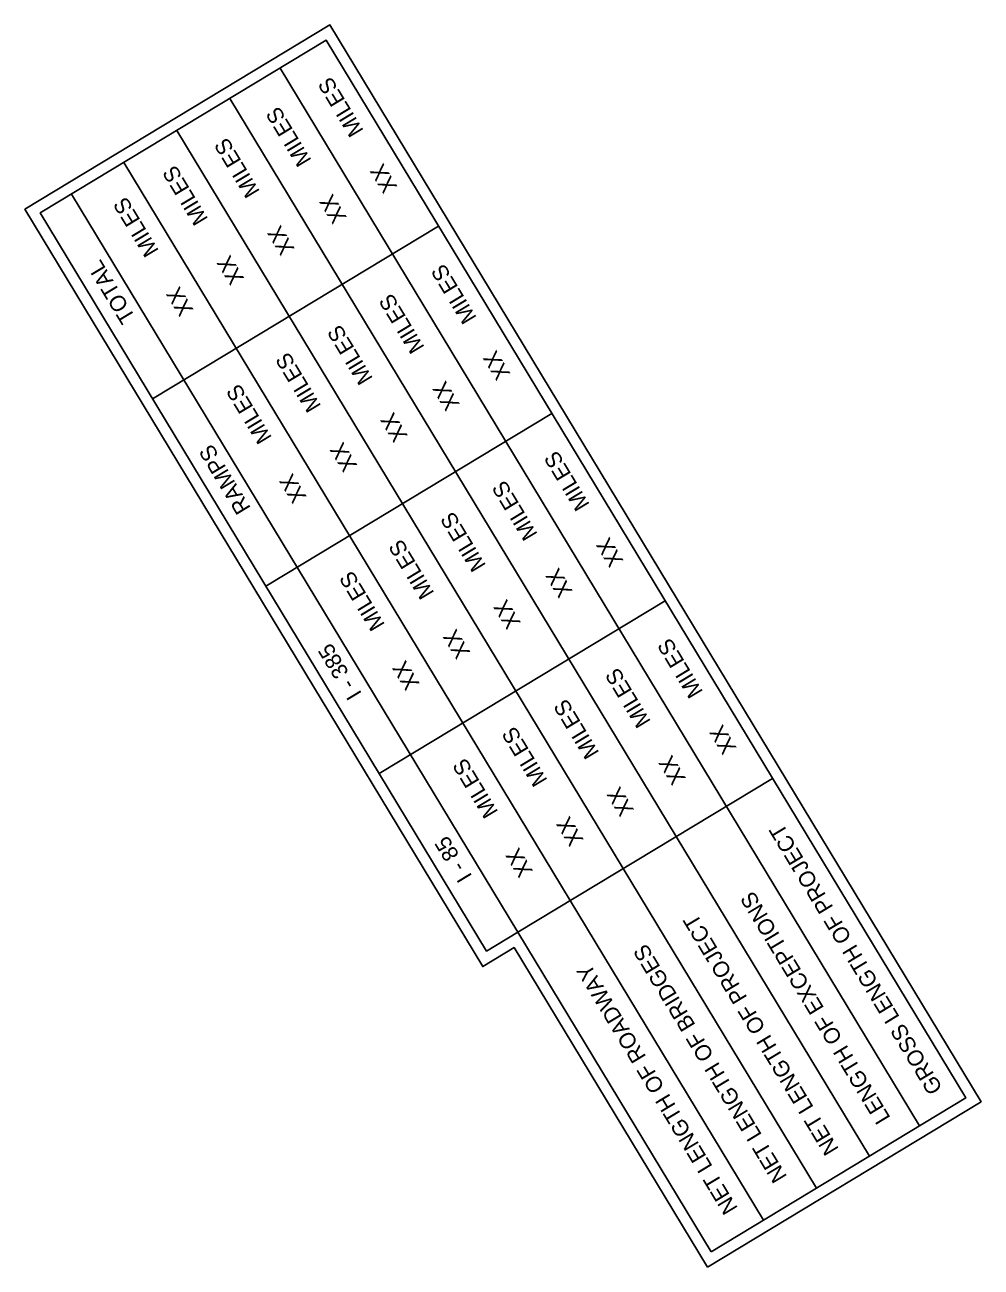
# Model space of a CAD drawing. Extents: x 2640307 to 2643631, y 679117 to 682232.
# Drawn here: x 2643233.2 to 2643532.1, y 681194.8 to 681583.2 of the extents above; entities that cross this region are included whole.
import ezdxf

# ---------------------------------------------------------------- set-up
doc = ezdxf.new("R2010")
doc.units = 0
doc.layers.add('Level 42', color=7, linetype='Continuous')
doc.layers.add('RD_SHT_TX', color=7, linetype='Continuous')

msp = doc.modelspace()

# ---------------------------------------------------------------- linework, layer by layer
at = {"layer": 'Level 42'}
for p, q in [((2643312.94, 681569.65), (2643512.83, 681238.95)), ((2643297.25, 681560.17), (2643497.15, 681229.47)), ((2643280.71, 681550.17), (2643480.61, 681219.47)), ((2643264.17, 681540.17), (2643464.07, 681209.48)), ((2643387.28, 681299.48), (2643247.78, 681530.26)), ((2643362.5, 681520.25), (2643273.12, 681466.22)), ((2643397.89, 681461.7), (2643308.52, 681407.67)), ((2643433.29, 681403.14), (2643343.91, 681349.12)), ((2643466.87, 681347.59), (2643387.28, 681299.48))]:
    msp.add_line(p, q, dxfattribs=at)
for points in [[(2643446.49, 681194.76), (2643386.09, 681294.67), (2643376.31, 681288.76), (2643233.19, 681525.53), (2643328.55, 681583.18), (2643532.07, 681246.49)], [(2643447.67, 681199.57), (2643387.28, 681299.48), (2643377.49, 681293.56), (2643237.99, 681524.35), (2643327.37, 681578.37), (2643527.26, 681247.67)]]:
    msp.add_lwpolyline(points, close=True, dxfattribs=at)

# ---------------------------------------------------------------- texts
at = {"layer": 'RD_SHT_TX'}
for s, height, p in [('MILES', 5, (2643339.2, 681550.09)), ('MILES', 5, (2643322.9, 681540.82)), ('MILES', 5, (2643306.77, 681531.07)), ('MILES', 5, (2643290.59, 681522.46)), ('XX', 5, (2643349.7, 681532.57)), ('XX', 5, (2643333.87, 681523)), ('MILES', 5, (2643275.19, 681512.56)), ('XX', 5, (2643317.62, 681513.18)), ('XX', 5, (2643301.85, 681503.88)), ('TOTAL', 5, (2643267.9, 681491.67)), ('MILES', 5, (2643374.54, 681491.63)), ('XX', 5, (2643286.02, 681494.08)), ('MILES', 5, (2643358.23, 681482.36)), ('MILES', 5, (2643342.1, 681472.61)), ('MILES', 5, (2643325.92, 681464)), ('XX', 5, (2643385.03, 681474.11)), ('XX', 5, (2643369.21, 681464.54)), ('MILES', 5, (2643310.52, 681454.11)), ('XX', 5, (2643352.95, 681454.72)), ('XX', 5, (2643337.19, 681445.42)), ('RAMPS', 5, (2643303.92, 681432.08)), ('MILES', 5, (2643409.87, 681433.18)), ('XX', 5, (2643321.36, 681435.62)), ('MILES', 5, (2643393.57, 681423.91)), ('MILES', 5, (2643377.44, 681414.15)), ('MILES', 5, (2643361.26, 681405.54)), ('XX', 5, (2643420.37, 681415.65)), ('XX', 5, (2643404.54, 681406.09)), ('MILES', 5, (2643345.86, 681395.65)), ('XX', 5, (2643388.29, 681396.26)), ('XX', 5, (2643372.52, 681386.97)), ('MILES', 5, (2643445.27, 681374.63)), ('I - 385', 5, (2643338.63, 681374.02)), ('XX', 5, (2643356.69, 681377.16)), ('MILES', 5, (2643428.96, 681365.35)), ('MILES', 5, (2643412.83, 681355.6)), ('MILES', 5, (2643396.65, 681346.99)), ('XX', 5, (2643455.76, 681357.1)), ('XX', 5, (2643439.93, 681347.54)), ('MILES', 5, (2643381.25, 681337.1)), ('XX', 5, (2643423.68, 681337.71)), ('XX', 5, (2643407.92, 681328.41)), ('GROSS LENGTH OF PROJECT', 5.0001, (2643520.2, 681250.65)), ('I - 85', 5, (2643373.12, 681316.96)), ('XX', 5, (2643392.09, 681318.61)), ('LENGTH OF EXCEPTIONS', 5.0001, (2643503.87, 681241.42)), ('NET LENGTH OF PROJECT', 5.0001, (2643487.74, 681231.67)), ('NET LENGTH OF BRIDGES', 5.0001, (2643471.56, 681223.06)), ('NET LENGTH OF ROADWAY', 5.0001, (2643456.16, 681213.17))]:
    msp.add_text(s, height=height, rotation=121.1513, dxfattribs=at).set_placement(p)

doc.saveas('drawing.dxf')
